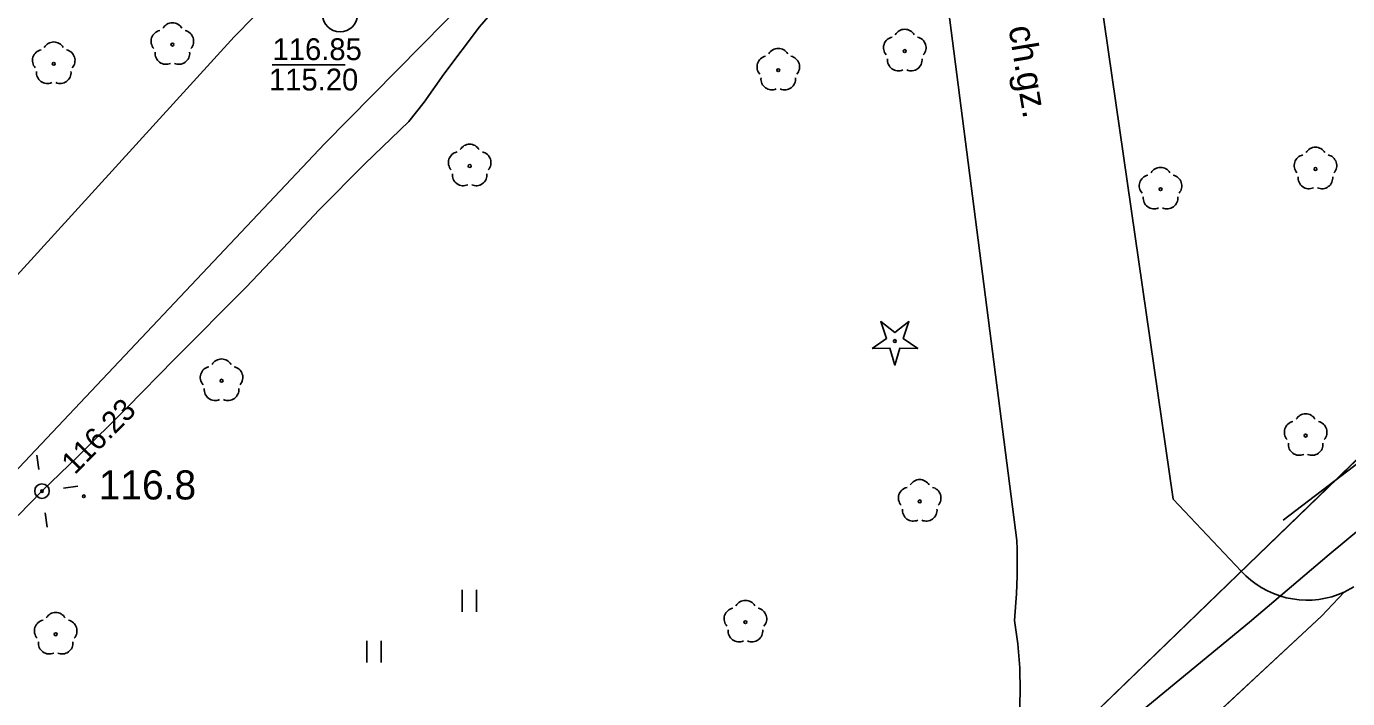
# Model space of a CAD drawing. Extents: x 6434771 to 6436222, y 5663454 to 5664782.
# Drawn here: x 6435538.2 to 6435583.63, y 5663841.43 to 5663864.53 of the extents above; entities that cross this region are included whole.
import ezdxf

# ---------------------------------------------------------------- set-up
doc = ezdxf.new("R2010")
doc.units = 0
for name, color, linetype in [('Warstwa 1', 7, 'Continuous'), ('Warstwa 10', 7, 'Continuous'), ('Warstwa 11', 7, 'Continuous'), ('Warstwa 12', 7, 'Continuous'), ('Warstwa 13', 7, 'Continuous'), ('Warstwa 14', 7, 'Continuous'), ('Warstwa 15', 7, 'Continuous'), ('Warstwa 2', 7, 'Continuous'), ('Warstwa 4', 7, 'Continuous'), ('Warstwa 5', 7, 'Continuous'), ('Warstwa 6', 7, 'Continuous'), ('Warstwa 8', 7, 'Continuous'), ('Warstwa 9', 7, 'Continuous')]:
    doc.layers.add(name, color=color, linetype=linetype)

msp = doc.modelspace()

# ---------------------------------------------------------------- linework, layer by layer
at = {"layer": 'Warstwa 1'}
msp.add_line((6435570.992, 5663837.121), (6435586.939, 5663852.54), dxfattribs=at)
msp.add_line((6435570.992, 5663837.121), (6435586.939, 5663852.54), dxfattribs=at)
at = {"layer": 'Warstwa 10'}
msp.add_lwpolyline([(6435567.276, 5663853.463), (6435567.778, 5663853.81), (6435567.576, 5663854.386), (6435568.061, 5663854.016), (6435568.546, 5663854.386), (6435568.344, 5663853.81), (6435568.846, 5663853.463), (6435568.236, 5663853.477), (6435568.061, 5663852.893), (6435567.886, 5663853.477)], close=True, dxfattribs=at)
msp.add_circle((6435568.061, 5663853.718), 0.05, dxfattribs=at)
at = {"layer": 'Warstwa 11'}
for centre in [(6435543.222, 5663863.907), (6435568.401, 5663863.684), (6435539.143, 5663863.247), (6435564.053, 5663863.027), (6435553.443, 5663859.734), (6435582.521, 5663859.631), (6435577.195, 5663858.937), (6435544.913, 5663852.352), (6435582.184, 5663850.468), (6435568.915, 5663848.207), (6435562.923, 5663844.055), (6435539.21, 5663843.64)]:
    msp.add_circle(centre, 0.05, dxfattribs=at)
for centre, start, end in [((6435543.222, 5663864.282), 30.1471, 149.8529), ((6435568.401, 5663864.059), 30.1471, 149.8529), ((6435539.143, 5663863.622), 30.1471, 149.8529), ((6435542.865, 5663864.023), 102.1471, 221.8529), ((6435543.579, 5663864.023), 318.1471, 77.8529), ((6435568.044, 5663863.8), 102.1471, 221.8529), ((6435568.758, 5663863.8), 318.1471, 77.8529), ((6435538.786, 5663863.363), 102.1471, 221.8529), ((6435539.5, 5663863.363), 318.1471, 77.8529), ((6435543.002, 5663863.604), 174.1471, 293.8529), ((6435543.442, 5663863.604), 246.1471, 5.8529), ((6435564.053, 5663863.402), 30.1471, 149.8529), ((6435563.696, 5663863.143), 102.1471, 221.8529), ((6435564.41, 5663863.143), 318.1471, 77.8529), ((6435568.181, 5663863.381), 174.1471, 293.8529), ((6435568.621, 5663863.381), 246.1471, 5.8529), ((6435538.923, 5663862.944), 174.1471, 293.8529), ((6435539.363, 5663862.944), 246.1471, 5.8529), ((6435563.833, 5663862.724), 174.1471, 293.8529), ((6435564.273, 5663862.724), 246.1471, 5.8529), ((6435553.443, 5663860.109), 30.1471, 149.8529), ((6435582.521, 5663860.006), 30.1471, 149.8529), ((6435553.086, 5663859.85), 102.1471, 221.8529), ((6435553.8, 5663859.85), 318.1471, 77.8529), ((6435582.164, 5663859.747), 102.1471, 221.8529), ((6435582.878, 5663859.747), 318.1471, 77.8529), ((6435553.223, 5663859.431), 174.1471, 293.8529), ((6435553.663, 5663859.431), 246.1471, 5.8529), ((6435577.195, 5663859.312), 30.1471, 149.8529), ((6435576.838, 5663859.053), 102.1471, 221.8529), ((6435577.552, 5663859.053), 318.1471, 77.8529), ((6435582.301, 5663859.328), 174.1471, 293.8529), ((6435582.741, 5663859.328), 246.1471, 5.8529), ((6435576.975, 5663858.634), 174.1471, 293.8529), ((6435577.415, 5663858.634), 246.1471, 5.8529), ((6435544.913, 5663852.727), 30.1471, 149.8529), ((6435544.556, 5663852.468), 102.1471, 221.8529), ((6435545.27, 5663852.468), 318.1471, 77.8529), ((6435544.693, 5663852.049), 174.1471, 293.8529), ((6435545.133, 5663852.049), 246.1471, 5.8529), ((6435581.827, 5663850.584), 102.1471, 221.8529), ((6435582.184, 5663850.843), 30.1471, 149.8529), ((6435582.541, 5663850.584), 318.1471, 77.8529), ((6435581.964, 5663850.165), 174.1471, 293.8529), ((6435582.404, 5663850.165), 246.1471, 5.8529), ((6435568.558, 5663848.323), 102.1471, 221.8529), ((6435568.915, 5663848.582), 30.1471, 149.8529), ((6435569.272, 5663848.323), 318.1471, 77.8529), ((6435568.695, 5663847.904), 174.1471, 293.8529), ((6435569.135, 5663847.904), 246.1471, 5.8529), ((6435562.566, 5663844.171), 102.1471, 221.8529), ((6435562.923, 5663844.43), 30.1471, 149.8529), ((6435563.28, 5663844.171), 318.1471, 77.8529), ((6435538.853, 5663843.756), 102.1471, 221.8529), ((6435539.21, 5663844.015), 30.1471, 149.8529), ((6435539.567, 5663843.756), 318.1471, 77.8529), ((6435562.703, 5663843.752), 174.1471, 293.8529), ((6435563.143, 5663843.752), 246.1471, 5.8529), ((6435538.99, 5663843.337), 174.1471, 293.8529), ((6435539.43, 5663843.337), 246.1471, 5.8529)]:
    msp.add_arc(centre, 0.375, start, end, dxfattribs=at)
at = {"layer": 'Warstwa 12'}
for points in [[(6435555.466, 5663866.478), (6435553.784, 5663864.518), (6435552.555, 5663862.894), (6435551.873, 5663861.934), (6435551.355, 5663861.268), (6435549.833, 5663859.81), (6435548.265, 5663858.226), (6435547.014, 5663856.898), (6435545.763, 5663855.569), (6435543.289, 5663853.1), (6435541.657, 5663851.427), (6435539.979, 5663849.762), (6435538.739, 5663848.56), (6435537.916, 5663847.717)], [(6435528.881, 5663795.616), (6435533.856, 5663800.554), (6435539.551, 5663806.088), (6435542.138, 5663808.709), (6435546.507, 5663812.75), (6435551.524, 5663817.65), (6435564.609, 5663830.373), (6435568.753, 5663834.665), (6435569.277, 5663834.98), (6435570.334, 5663835.827), (6435571.826, 5663837.072), (6435574.267, 5663839.086), (6435576.763, 5663841.179), (6435580.251, 5663844.052), (6435582.992, 5663846.385), (6435586.22, 5663849.061)]]:
    msp.add_lwpolyline(points, dxfattribs=at)
at = {"layer": 'Warstwa 13'}
msp.add_circle((6435540.177, 5663848.383), 0.045, dxfattribs=at)
at = {"layer": 'Warstwa 14'}
msp.add_line((6435549.159, 5663863.211), (6435546.65, 5663863.211), dxfattribs=at)
msp.add_circle((6435538.739, 5663848.56), 0.045, dxfattribs=at)
at = {"layer": 'Warstwa 15'}
msp.add_circle((6435548.985, 5663864.944), 0.6, dxfattribs=at)
at = {"layer": 'Warstwa 2'}
msp.add_circle((6435538.739, 5663848.56), 0.25, dxfattribs=at)
at = {"layer": 'Warstwa 4'}
for points in [[(6435605.923, 5663864.472), (6435611.396, 5663865.567), (6435600.555, 5663862.167), (6435581.409, 5663847.567)], [(6435538.635, 5663849.303), (6435538.565, 5663849.798)], [(6435539.482, 5663848.664), (6435539.977, 5663848.734)], [(6435538.843, 5663847.817), (6435538.913, 5663847.322)]]:
    msp.add_lwpolyline(points, dxfattribs=at)
at = {"layer": 'Warstwa 5'}
for p, q in [((6435548.451, 5663860.494), (6435567.951, 5663880.281)), ((6435567.951, 5663880.281), (6435572.259, 5663846.867)), ((6435535.839, 5663847.135), (6435548.451, 5663860.494)), ((6435572.259, 5663846.867), (6435572.267, 5663846.562)), ((6435572.267, 5663846.562), (6435572.27, 5663846.256)), ((6435572.263, 5663845.644), (6435572.268, 5663845.95)), ((6435572.268, 5663845.95), (6435572.27, 5663846.256)), ((6435572.254, 5663845.339), (6435572.263, 5663845.644)), ((6435553.181, 5663844.415), (6435553.181, 5663845.165)), ((6435553.681, 5663844.415), (6435553.681, 5663845.165)), ((6435572.223, 5663844.728), (6435572.24, 5663845.033)), ((6435572.24, 5663845.033), (6435572.254, 5663845.339)), ((6435572.201, 5663844.423), (6435572.223, 5663844.728)), ((6435572.176, 5663844.118), (6435572.201, 5663844.423)), ((6435572.176, 5663844.118), (6435572.29, 5663843.307)), ((6435549.904, 5663842.666), (6435549.904, 5663843.416)), ((6435550.404, 5663842.666), (6435550.404, 5663843.416)), ((6435572.29, 5663843.307), (6435572.356, 5663842.491)), ((6435572.356, 5663842.491), (6435572.374, 5663841.672)), ((6435572.344, 5663840.854), (6435572.374, 5663841.672))]:
    msp.add_line(p, q, dxfattribs=at)
at = {"layer": 'Warstwa 6'}
for points in [[(6435497.48, 5663799.45), (6435506.7, 5663789.56), (6435508.43, 5663787.33), (6435509.75, 5663785.12), (6435510.77, 5663783.65), (6435512.59, 5663782.25), (6435514.22, 5663781.8), (6435527.892, 5663795.248), (6435570.992, 5663837.121), (6435586.939, 5663852.54), (6435599.429, 5663860.81), (6435608.979, 5663864.176), (6435617.268, 5663864.926), (6435627.619, 5663865.031), (6435640.832, 5663867.732), (6435649.164, 5663870.462), (6435662.228, 5663877.475)], [(6435662.228, 5663877.475), (6435649.164, 5663870.462), (6435640.832, 5663867.732), (6435627.619, 5663865.031), (6435617.268, 5663864.926), (6435608.979, 5663864.176), (6435599.429, 5663860.81), (6435586.939, 5663852.54), (6435570.992, 5663837.121), (6435527.892, 5663795.248)], [(6435583.508, 5663845.088), (6435583.298, 5663845.002), (6435583.083, 5663844.931), (6435582.862, 5663844.877), (6435582.639, 5663844.838), (6435582.413, 5663844.817), (6435582.186, 5663844.812), (6435581.959, 5663844.824), (6435581.734, 5663844.852), (6435581.511, 5663844.897), (6435581.293, 5663844.959), (6435581.079, 5663845.036), (6435580.872, 5663845.128), (6435580.672, 5663845.236), (6435580.481, 5663845.358), (6435580.299, 5663845.494), (6435580.127, 5663845.643), (6435579.967, 5663845.804)], [(6435583.508, 5663845.088), (6435582.732, 5663844.262), (6435578.347, 5663840.19), (6435575.766, 5663837.756), (6435572.445, 5663834.487), (6435568.337, 5663830.514), (6435563.878, 5663826.121), (6435558.354, 5663820.764), (6435553.861, 5663816.312), (6435548.462, 5663811.023), (6435544.479, 5663807.106), (6435540.739, 5663803.382), (6435539.954, 5663802.753), (6435536.049, 5663803.24)], [(6435583.836, 5663845.265), (6435583.508, 5663845.088)]]:
    msp.add_lwpolyline(points, dxfattribs=at)
at = {"layer": 'Warstwa 8'}
for p, q in [((6435582.732, 5663844.262), (6435583.508, 5663845.088)), ((6435583.508, 5663845.088), (6435583.836, 5663845.265)), ((6435578.347, 5663840.19), (6435582.732, 5663844.262))]:
    msp.add_line(p, q, dxfattribs=at)
at = {"layer": 'Warstwa 9'}
for p, q in [((6435572.429, 5663884.297), (6435577.627, 5663848.282)), ((6435548.451, 5663860.494), (6435567.951, 5663880.281)), ((6435567.951, 5663880.281), (6435572.259, 5663846.867)), ((6435545.345, 5663864.172), (6435558.649, 5663877.712)), ((6435532.474, 5663850.046), (6435545.345, 5663864.172)), ((6435535.839, 5663847.135), (6435548.451, 5663860.494)), ((6435577.627, 5663848.282), (6435579.967, 5663845.804)), ((6435572.259, 5663846.867), (6435572.267, 5663846.562)), ((6435572.267, 5663846.562), (6435572.27, 5663846.256)), ((6435572.263, 5663845.644), (6435572.268, 5663845.95)), ((6435572.268, 5663845.95), (6435572.27, 5663846.256)), ((6435572.254, 5663845.339), (6435572.263, 5663845.644)), ((6435579.967, 5663845.804), (6435580.127, 5663845.643)), ((6435580.127, 5663845.643), (6435580.299, 5663845.494)), ((6435580.299, 5663845.494), (6435580.481, 5663845.358)), ((6435580.481, 5663845.358), (6435580.672, 5663845.236)), ((6435572.223, 5663844.728), (6435572.24, 5663845.033)), ((6435572.24, 5663845.033), (6435572.254, 5663845.339)), ((6435580.672, 5663845.236), (6435580.872, 5663845.128)), ((6435580.872, 5663845.128), (6435581.079, 5663845.036)), ((6435581.079, 5663845.036), (6435581.293, 5663844.959)), ((6435581.293, 5663844.959), (6435581.511, 5663844.897)), ((6435582.732, 5663844.262), (6435583.508, 5663845.088)), ((6435582.862, 5663844.877), (6435583.083, 5663844.931)), ((6435583.083, 5663844.931), (6435583.298, 5663845.002)), ((6435583.298, 5663845.002), (6435583.508, 5663845.088)), ((6435572.201, 5663844.423), (6435572.223, 5663844.728)), ((6435581.511, 5663844.897), (6435581.734, 5663844.852)), ((6435581.734, 5663844.852), (6435581.959, 5663844.824)), ((6435581.959, 5663844.824), (6435582.186, 5663844.812)), ((6435582.186, 5663844.812), (6435582.413, 5663844.817)), ((6435582.413, 5663844.817), (6435582.639, 5663844.838)), ((6435582.639, 5663844.838), (6435582.862, 5663844.877)), ((6435572.176, 5663844.118), (6435572.201, 5663844.423)), ((6435572.176, 5663844.118), (6435572.29, 5663843.307)), ((6435578.347, 5663840.19), (6435582.732, 5663844.262)), ((6435572.29, 5663843.307), (6435572.356, 5663842.491)), ((6435572.356, 5663842.491), (6435572.374, 5663841.672)), ((6435572.344, 5663840.854), (6435572.374, 5663841.672))]:
    msp.add_line(p, q, dxfattribs=at)

# ---------------------------------------------------------------- texts
at = {"layer": 'Warstwa 13'}
msp.add_text('116.8', height=1, dxfattribs=at).set_placement((6435540.691, 5663848.273))
at = {"layer": 'Warstwa 14'}
msp.add_text('115.20', height=0.75, dxfattribs=at).set_placement((6435546.544, 5663862.33))
msp.add_text('116.23', height=0.75, rotation=45.4642, dxfattribs=at).set_placement((6435539.867, 5663849.101))
at = {"layer": 'Warstwa 6'}
msp.add_text('116.85', height=0.75, dxfattribs=at).set_placement((6435546.667, 5663863.374))
at = {"layer": 'Warstwa 9'}
msp.add_text('ch.gz.', height=0.9, rotation=279.3456, dxfattribs=at).set_placement((6435571.964, 5663864.497))

doc.saveas('drawing.dxf')
